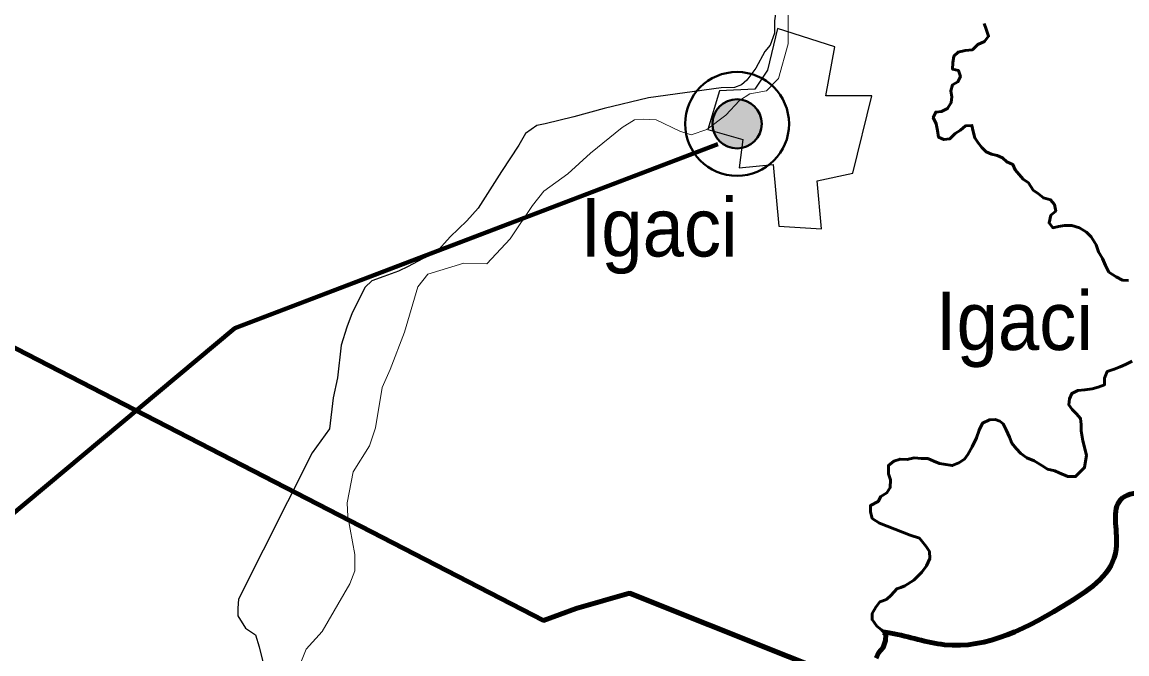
# Model space of a CAD drawing. Extents: x 553962 to 842807, y 8883888 to 9032388.
# Drawn here: x 753512 to 762958, y 8939742 to 8945147 of the extents above; entities that cross this region are included whole.
import ezdxf

# ---------------------------------------------------------------- set-up
doc = ezdxf.new("R2010")
doc.units = 0
doc.header["$LTSCALE"] = 200
for name, color, linetype, lineweight in [('12', 7, 'Continuous', 25), ('14', 7, 'Continuous', 13), ('21', 7, 'Continuous', 25), ('24', 7, 'Continuous', 25), ('28', 7, 'Continuous', 40), ('41', 7, 'Continuous', 40), ('9', 7, 'Continuous', 90)]:
    doc.layers.add(name, color=color, linetype=linetype, lineweight=lineweight)

msp = doc.modelspace()

# ---------------------------------------------------------------- hatches: boundary and pattern name
at = {"layer": '28'}
msp.add_hatch(color=256, dxfattribs=at).paths.add_polyline_path([(759835.2, 8944276.1, 1), (759414.4, 8944276.1, 1)])

# ---------------------------------------------------------------- linework, layer by layer
at = {"layer": '12'}
for points in [[(759983.7, 8945452), (759944.5, 8945159.2), (759944.1, 8945052.2), (759908, 8944950.4), (759862, 8944894.4), (759785, 8944751.9), (759708.2, 8944650.2), (759662.2, 8944609.5), (759602.9, 8944588), (759488.4, 8944585.1)], [(759488.4, 8944585.1), (758867.1, 8944498.9), (758489.8, 8944407.9), (758229.7, 8944337.1), (757985, 8944276.4), (757913.6, 8944261.2), (757816.6, 8944195.2), (757760.2, 8944093.4), (757611.6, 8943869.5), (757411.8, 8943554.1), (757314.6, 8943447.3), (757171.4, 8943310), (757048.7, 8943172.7), (756936.4, 8943121.9), (756813.9, 8943055.9), (756729.6, 8943015), (756604.7, 8942969.7), (756502.7, 8942934.3), (756446.4, 8942878.3), (756333.6, 8942659.5), (756287.3, 8942537.3), (756240.8, 8942384.6), (756209.2, 8942104.5), (756173, 8941931.3), (756141.4, 8941666.5), (755992.9, 8941463), (755361.7, 8940211), (755356.3, 8940134.6), (755356.1, 8940068.4), (755421.9, 8939961.3), (755508.3, 8939905.1), (755538.5, 8939803.2), (755593.8, 8939584)]]:
    msp.add_lwpolyline(points, dxfattribs=at)
at = {"layer": '12', "lineweight": 40}
msp.add_spline([(761549.2, 8957020.4), (762383.1, 8955993.9), (763257, 8954902.9), (764214.4, 8953717.3), (766168.2, 8951324.4), (767086.6, 8950171.6), (770317.8, 8946184.2), (771971, 8944146), (773006.3, 8942876.2), (773223.4, 8942642.3), (773373.7, 8942274.8), (774008.3, 8940921.5), (774359, 8940136.3), (774475.8, 8939919.1), (774642.8, 8939785.5), (774893.3, 8939668.5), (775511.2, 8939484.7), (775928.6, 8939267.5), (776078.9, 8939184), (776379.5, 8938916.7), (776680.1, 8938749.6), (776830.4, 8938582.6), (777398.1, 8938348.7), (777899.1, 8938231.7), (778550.4, 8938482.3), (779134.8, 8938866.6), (779452.1, 8939250.8), (779569, 8939384.5), (779685.9, 8939351.1), (779852.9, 8939217.4), (780086.7, 8939217.4), (780604.3, 8939451.3), (781055.2, 8939618.4), (781439.3, 8939618.4), (781823.3, 8939518.1), (782090.5, 8939401.2), (782290.9, 8939367.8), (782524.7, 8939518.1), (782858.7, 8939618.4), (783192.6, 8939651.8), (783509.9, 8939818.9), (783910.7, 8940119.6), (784278.1, 8940336.8), (784625.2, 8940434.5)], degree=3, dxfattribs=at)
at = {"layer": '14'}
for points in [[(756356.5, 8940591.2), (756296.6, 8940917.4), (756291.9, 8941034.6), (756343.8, 8941299.3), (756482.2, 8941523.2), (756533.7, 8941676), (756591, 8942022.3), (756657.8, 8942175), (756781.3, 8942495.7), (756894.8, 8942882.6), (756981.8, 8942989.4), (757287.8, 8943085.7), (757486.4, 8943080.2), (757685.9, 8943293.8), (757875.4, 8943578.7), (757972.7, 8943700.8), (758177, 8943848.1), (758371.2, 8944026.1), (758642, 8944244.6), (758749.2, 8944310.6), (758825.7, 8944315.6), (758932.7, 8944310.3), (759136.1, 8944213.1), (759232.8, 8944182.4), (759365.4, 8944228), (759528.8, 8944349.9), (759646.5, 8944477.1), (759733.3, 8944533), (759876, 8944558.2), (759978.3, 8944665), (760060.9, 8944960.3), (760062.2, 8945306.7)], [(755832.9, 8939512.3), (755940.9, 8939782.1), (756079, 8939934.6), (756314.8, 8940341.7), (756356, 8940453.7), (756356.5, 8940591.2)]]:
    msp.add_lwpolyline(points, dxfattribs=at)
at = {"layer": '21'}
msp.add_lwpolyline([(759971.8, 8945092.7), (759884.4, 8944737), (759777.9, 8944573.9), (759473.6, 8944557.9), (759374.4, 8944228.2), (759675.4, 8944141.8), (759642.3, 8943899.6), (759934.4, 8943928.7), (759980.7, 8943402.3), (760347, 8943377.8), (760309.6, 8943788.8), (760615.6, 8943855.9), (760776.1, 8944516.6), (760383.6, 8944516.3), (760460.4, 8944936.4)], close=True, dxfattribs=at)
at = {"layer": '24', "lineweight": 53}
for points in [[(761737.3, 8945134.7), (761755.2, 8945087.5), (761775.2, 8945026.3), (761739.2, 8944980.7), (761683.1, 8944955.6), (761637, 8944910), (761576, 8944905.3), (761514.8, 8944890.4), (761479, 8944855), (761468.4, 8944799), (761468, 8944743), (761518.8, 8944732.5), (761533.7, 8944681.5), (761513.1, 8944635.7), (761467.1, 8944610.6), (761451.5, 8944559.7), (761461.3, 8944508.7), (761455.9, 8944457.8), (761425, 8944407.1), (761374, 8944381.9), (761323.1, 8944377.2), (761302.4, 8944331.5), (761327.5, 8944275.3), (761337.3, 8944219.2), (761347.1, 8944163.1), (761392.7, 8944142.4), (761443.6, 8944147.2), (761489.7, 8944192.7), (761535.7, 8944223), (761576.6, 8944258.4), (761632.6, 8944263.1), (761642.4, 8944212.1), (761657.3, 8944156), (761687.5, 8944115.1), (761717.7, 8944074.1), (761753.1, 8944038.2), (761798.7, 8944017.6), (761849.5, 8944007), (761895.2, 8943986.4), (761930.5, 8943950.5), (761981.2, 8943929.8), (762001.3, 8943883.8), (762036.6, 8943842.8), (762071.9, 8943801.9), (762117.5, 8943771), (762157.7, 8943709.6), (762203.3, 8943678.8), (762243.7, 8943642.8), (762304.7, 8943627.2), (762340, 8943586.2), (762349.8, 8943530.1), (762308.8, 8943494.7), (762293.1, 8943428.6), (762323.4, 8943387.7), (762374.3, 8943397.5), (762425.2, 8943407.4), (762486.2, 8943407), (762552.2, 8943386.2), (762613, 8943350.1), (762653.4, 8943309.1), (762693.7, 8943242.6), (762713.6, 8943181.4), (762748.8, 8943125.1), (762773.8, 8943063.8), (762803.9, 8943007.6)], [(762803.9, 8943007.6), (762864.7, 8942966.5), (762920.5, 8942940.7), (762971.3, 8942935.2)], [(763002.2, 8942247.4), (762946, 8942217.2), (762900.1, 8942197.1), (762849.1, 8942177), (762787.9, 8942157.1), (762767.2, 8942101.2), (762766.8, 8942045.1), (762710.7, 8942025.1), (762659.8, 8942010.2), (762598.7, 8942000.3), (762537.6, 8941995.7), (762486.6, 8941970.5), (762465.9, 8941924.8), (762460.5, 8941873.9), (762490.7, 8941832.9), (762526.1, 8941797.1), (762561.4, 8941756.1), (762566.1, 8941705.1), (762565.7, 8941649.1)], [(762565.7, 8941649.1), (762580.6, 8941564.2), (762580.6, 8941564.2), (762611.1, 8941442.4), (762595.8, 8941335.7), (762519.6, 8941259.6), (762453.6, 8941259.6), (762377.4, 8941292.5), (762340.6, 8941308.9), (762279.2, 8941321.2), (762230.1, 8941353.9), (762164.6, 8941394.8), (762103.2, 8941419.3), (762051.3, 8941456.8), (762010.3, 8941499.8), (761975, 8941545.9), (761955, 8941597), (761924.9, 8941658.3), (761899.8, 8941709.4), (761871.3, 8941731.8), (761831, 8941748.4), (761783.1, 8941745.8), (761721.9, 8941715.6), (761696, 8941655.9), (761672.3, 8941589.5), (761634.4, 8941513.7), (761596.5, 8941447.3), (761568.1, 8941409.3), (761520.8, 8941376.1), (761463.9, 8941352.4), (761392.8, 8941366.6), (761355, 8941371.4), (761307.6, 8941390.3), (761257, 8941413), (761201, 8941413.3), (761140, 8941418.8), (761080.2, 8941404.6), (761018.6, 8941409.3), (760966.5, 8941390.3), (760919.1, 8941352.4), (760920.8, 8941343.8), (760920.4, 8941282.7), (760935.3, 8941231.7), (760934.8, 8941165.4), (760904, 8941119.8), (760852.9, 8941089.6), (760830.3, 8941047.1), (760764.8, 8941010.3), (760764.8, 8941010.3), (760764.8, 8940957.1), (760780.4, 8940901.6), (760841.2, 8940860.4), (761104.9, 8940756.8), (761184.4, 8940731.1), (761241.3, 8940660), (761269.7, 8940617.3), (761272.5, 8940557.8), (761245.1, 8940495.9), (761203.9, 8940441), (761135.3, 8940372.3), (761059.8, 8940324.2), (761025.5, 8940310.4), (760989.9, 8940299.1), (760943.7, 8940243.4), (760902.8, 8940208)], [(760902.8, 8940208), (760846.7, 8940188), (760810.8, 8940142.4), (760779.9, 8940086.5), (760779.6, 8940035.6), (760819.8, 8939979.3), (760860.3, 8939948.5), (760895.7, 8939907.5), (760895.3, 8939856.6), (760874.5, 8939795.6), (760833.5, 8939750), (760812.9, 8939704.3)]]:
    msp.add_lwpolyline(points, dxfattribs=at)
at = {"layer": '28', "lineweight": 80}
msp.add_lwpolyline([(745375.5, 8936603.4), (745835.3, 8936788.7), (747785.1, 8937257.7), (749903.6, 8938158.1), (749978.6, 8938702.2), (750466, 8939208.7), (752134.6, 8940015.3), (753221.9, 8940765.7), (755331.2, 8942528.6), (759461.4, 8944103)], dxfattribs=at)
at = {"layer": '28'}
for radius in [444.4, 210.4]:
    msp.add_circle((759624.8, 8944276.1), radius, dxfattribs=at)
at = {"layer": '9'}
for points in [[(760739.9, 8939450.1), (758705.7, 8940260.8), (758249.4, 8940131.7), (757970.6, 8940028.8), (750978.7, 8943631.9), (743914.7, 8940037.6)], [(760739.9, 8939450.1), (758705.7, 8940260.8), (758249.4, 8940131.7), (757970.6, 8940028.8), (750978.7, 8943631.9), (743914.7, 8940037.6)], [(760879.8, 8939925.9), (760895.7, 8939907.5), (760895.3, 8939856.6), (760874.5, 8939795.6), (760833.5, 8939750), (760812.9, 8939704.3)]]:
    msp.add_lwpolyline(points, dxfattribs=at)
msp.add_spline([(779358.3, 8951316.5), (778152, 8950383.2), (776870.5, 8948893), (775858.2, 8948102.8), (775096.9, 8948098.3), (774081.6, 8948143.1), (772814, 8947781.5), (772105.2, 8947296.6), (771547.4, 8947166.9), (771322, 8946330.6), (771374.4, 8945875.5), (771395.1, 8945546.1), (769593.3, 8944681.6), (768541.6, 8943918.8), (767488.3, 8942812.2), (766189.2, 8941452.3), (765366.7, 8940769), (764084.5, 8940646.2), (763321.5, 8941097.2), (762890.2, 8941044.2), (762866.3, 8940639.2), (762461.9, 8940181.4), (761397.4, 8939821), (760940.2, 8939919.5), (760875, 8939930.2)], degree=3, dxfattribs=at)

# ---------------------------------------------------------------- texts
at = {"layer": '41', "width": 0.95}
for p in [(758287.4, 8943141.7), (761325, 8942341.6)]:
    msp.add_text('Igaci', height=500, dxfattribs=at).set_placement(p)

doc.saveas('drawing.dxf')
